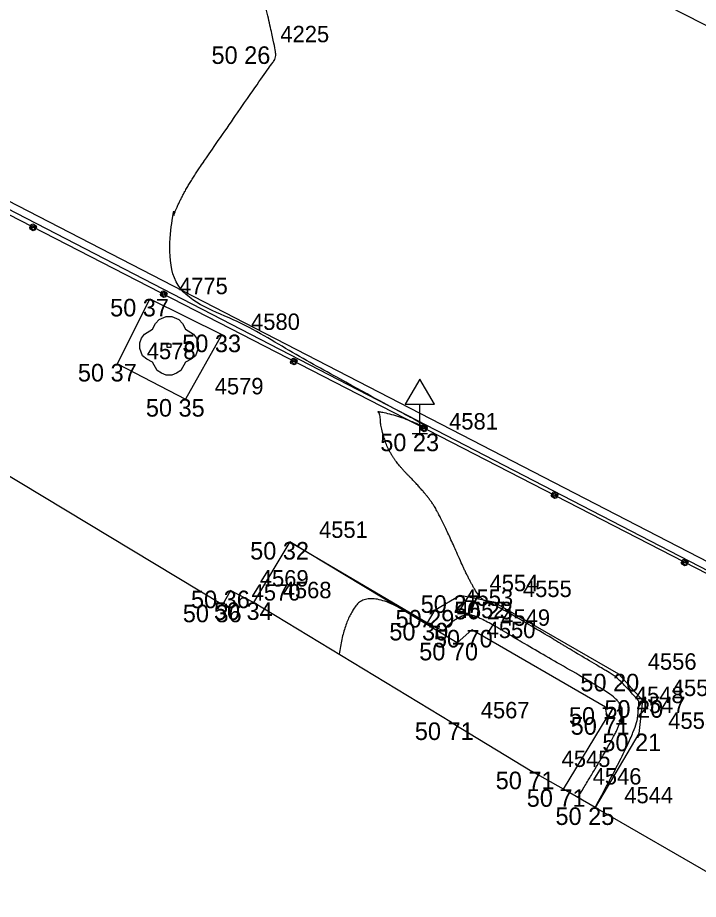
# Model space of a CAD drawing. Extents: x -704017 to -701500, y -1008977 to -1008450.
# Drawn here: x -701790.22 to -701778.61, y -1008943.87 to -1008928.82 of the extents above; entities that cross this region are included whole.
import ezdxf

# ---------------------------------------------------------------- set-up
doc = ezdxf.new("R2010")
doc.units = 0
for name, color, linetype in [('Z_body', 7, 'Continuous'), ('Z_body_cisla', 7, 'Continuous'), ('Z_body_vysky', 7, 'Continuous'), ('Z_budovy', 7, 'Continuous'), ('Z_dopravni_znaceni', 7, 'Continuous'), ('Z_komunikace', 7, 'Continuous'), ('Z_obruby', 7, 'Continuous'), ('Z_rozhrani_ploch', 7, 'Continuous'), ('Z_vrstevnice_vedlejsi', 7, 'Continuous'), ('Z_vstupy', 7, 'Continuous'), ('Z_zabradli', 7, 'Continuous'), ('Z_zelen_jednotliva', 7, 'Continuous')]:
    doc.layers.add(name, color=color, linetype=linetype)

# ---------------------------------------------------------------- blocks, each defined once
blk = doc.blocks.new('POINT_DISPLAY')
blk.add_line((0, 0), (0, 0))
blk = doc.blocks.new('Z530')
for p, q in [((-0.05, 0.03), (-0.03, 0.05)), ((-0.05, -0.03), (-0.05, 0.03)), ((-0.03, 0.05), (0.03, 0.05)), ((-0.03, -0.03), (-0.03, 0.03)), ((-0.03, 0.03), (0.03, 0.03)), ((-0.03, -0.03), (0.03, 0.03)), ((0.03, 0.05), (0.05, 0.03)), ((0.03, 0.03), (0.03, -0.03)), ((0.05, 0.03), (0.05, -0.03)), ((-0.03, -0.05), (-0.05, -0.03)), ((0.03, -0.03), (-0.03, -0.03)), ((0.03, -0.05), (-0.03, -0.05)), ((0.05, -0.03), (0.03, -0.05))]:
    blk.add_line(p, q)
blk = doc.blocks.new('Z527')
for p, q in [((0, 0.93), (-0.25, 0.5)), ((0.25, 0.5), (0, 0.93)), ((-0.25, 0.5), (0.25, 0.5)), ((0, 0), (0, 0.5)), ((-0.13, 0), (0.13, 0))]:
    blk.add_line(p, q)
blk = doc.blocks.new('Z24')
for p, q in [((-0.17, 0.45), (-0.05, 0.5)), ((-0.05, 0.5), (0.05, 0.5)), ((0.05, 0.5), (0.17, 0.45)), ((-0.28, 0.28), (-0.23, 0.38)), ((-0.23, 0.38), (-0.17, 0.45)), ((0.17, 0.45), (0.23, 0.38)), ((0.23, 0.38), (0.28, 0.28)), ((-0.47, 0.13), (-0.42, 0.2)), ((-0.42, 0.2), (-0.28, 0.28)), ((0.28, 0.28), (0.42, 0.2)), ((0.42, 0.2), (0.47, 0.13)), ((-0.5, 0.05), (-0.47, 0.13)), ((-0.5, -0.05), (-0.5, 0.05)), ((-0.03, -0.03), (-0.03, 0.03)), ((-0.03, 0.03), (0.03, 0.03)), ((0.03, 0.03), (0.03, -0.03)), ((0.47, 0.13), (0.5, 0.05)), ((0.5, 0.05), (0.5, -0.05)), ((-0.45, -0.17), (-0.5, -0.05)), ((0.03, -0.03), (-0.03, -0.03)), ((0.5, -0.05), (0.45, -0.17)), ((-0.38, -0.23), (-0.45, -0.17)), ((-0.28, -0.28), (-0.38, -0.23)), ((-0.2, -0.42), (-0.28, -0.28)), ((0.28, -0.28), (0.2, -0.42)), ((0.38, -0.23), (0.28, -0.28)), ((0.45, -0.17), (0.38, -0.23)), ((-0.13, -0.47), (-0.2, -0.42)), ((0.2, -0.42), (0.13, -0.47)), ((-0.05, -0.5), (-0.13, -0.47)), ((0.05, -0.5), (-0.05, -0.5)), ((0.13, -0.47), (0.05, -0.5))]:
    blk.add_line(p, q)

msp = doc.modelspace()

# ---------------------------------------------------------------- linework, layer by layer
at = {"layer": 'Z_budovy'}
for p, q in [((-701786.73, -1008938.84), (-701795, -1008933.86)), ((-701786.59, -1008938.6), (-701786.73, -1008938.84)), ((-701786.2, -1008938.8), (-701786.59, -1008938.6)), ((-701782.82, -1008940.85), (-701786.2, -1008938.8)), ((-701780.91, -1008941.99), (-701781.44, -1008941.69)), ((-701780.37, -1008942.3), (-701780.91, -1008941.99)), ((-701777.65, -1008943.87), (-701780.37, -1008942.3))]:
    msp.add_line(p, q, dxfattribs=at)
at = {"layer": 'Z_komunikace'}
for p, q in [((-701786.47, -1008924.83), (-701776.64, -1008929.9)), ((-701792.33, -1008930.94), (-701777.69, -1008938.5))]:
    msp.add_line(p, q, dxfattribs=at)
at = {"layer": 'Z_obruby'}
msp.add_line((-701777.73, -1008938.63), (-701794.29, -1008930.07), dxfattribs=at)
at = {"layer": 'Z_rozhrani_ploch'}
for p, q in [((-701788.52, -1008934.73), (-701787.97, -1008933.62)), ((-701787.97, -1008933.62), (-701786.74, -1008934.23)), ((-701786.74, -1008934.23), (-701787.36, -1008935.33)), ((-701788.52, -1008934.73), (-701787.36, -1008935.33)), ((-701785.58, -1008937.77), (-701786.2, -1008938.8)), ((-701782.72, -1008939.49), (-701785.58, -1008937.77)), ((-701785.58, -1008937.77), (-701783.23, -1008939.15)), ((-701783.1, -1008938.93), (-701782.67, -1008938.68)), ((-701782.67, -1008938.68), (-701782.1, -1008938.79)), ((-701782.1, -1008938.79), (-701779.97, -1008940.02)), ((-701783.23, -1008939.15), (-701783.1, -1008938.93)), ((-701782.47, -1008939.27), (-701782.72, -1008939.49)), ((-701780.19, -1008940.59), (-701782.47, -1008939.27)), ((-701779.97, -1008940.02), (-701779.56, -1008940.47)), ((-701779.56, -1008940.47), (-701779.62, -1008941.04)), ((-701780.16, -1008940.76), (-701780.19, -1008940.59)), ((-701780.91, -1008941.99), (-701780.16, -1008940.76)), ((-701779.62, -1008941.04), (-701780.37, -1008942.3))]:
    msp.add_line(p, q, dxfattribs=at)
at = {"layer": 'Z_vrstevnice_vedlejsi'}
for points in [[(-701780.37, -1008942.3), (-701779.663, -1008941.018), (-701779.619, -1008940.498), (-701779.622, -1008940.482), (-701779.992, -1008940.076), (-701780.22, -1008939.945), (-701782.116, -1008938.81), (-701782.385, -1008938.735), (-701783.015, -1008937.3), (-701783.273, -1008936.923), (-701783.853, -1008936.331), (-701784.027, -1008935.822), (-701784.036, -1008935.582), (-701784.106, -1008935.525), (-701783.661, -1008935.639), (-701783.182, -1008935.849), (-701783.401, -1008935.701), (-701784.062, -1008935.357), (-701785.982, -1008934.283), (-701788.263, -1008933.04), (-701785.923, -1008929.65), (-701785.816, -1008929.525), (-701785.823, -1008929.336), (-701786.355, -1008927.07), (-701787.003, -1008925.385), (-701787.033, -1008925.191), (-701786.912, -1008924.761), (-701786.955, -1008924.578), (-701786.813, -1008924.647), (-701786.464, -1008924.816), (-701781.758, -1008927.096), (-701779.49, -1008926.403), (-701778.887, -1008926.304), (-701778.837, -1008926.233)], [(-701780.663, -1008942.132), (-701780.256, -1008941.463), (-701779.933, -1008940.878), (-701779.913, -1008940.641), (-701779.931, -1008940.541), (-701780.099, -1008940.355), (-701781.47, -1008939.57), (-701782.313, -1008939.066), (-701782.563, -1008938.996), (-701782.777, -1008939.104), (-701782.905, -1008939.217), (-701782.975, -1008939.32), (-701784.225, -1008938.585), (-701784.653, -1008939.107), (-701784.738, -1008939.686)]]:
    msp.add_open_spline(points, degree=2, dxfattribs=at)
at = {"layer": 'Z_vstupy'}
msp.add_line((-701782.82, -1008940.85), (-701781.44, -1008941.69), dxfattribs=at)
at = {"layer": 'Z_zabradli'}
msp.add_line((-701777.73, -1008938.69), (-701791.57, -1008931.57), dxfattribs=at)

# ---------------------------------------------------------------- block references
at = {"layer": 'Z_body'}
for p in [(-701786.24, -1008929.31), (-701787.97, -1008933.62), (-701786.74, -1008934.23), (-701788.52, -1008934.73), (-701787.36, -1008935.33), (-701783.36, -1008935.92), (-701785.58, -1008937.77), (-701786.59, -1008938.6), (-701782.67, -1008938.68), (-701786.73, -1008938.84), (-701786.2, -1008938.8), (-701782.1, -1008938.79), (-701783.1, -1008938.93), (-701783.23, -1008939.15), (-701782.47, -1008939.27), (-701782.72, -1008939.49), (-701779.97, -1008940.02), (-701779.56, -1008940.47), (-701780.19, -1008940.59), (-701780.16, -1008940.76), (-701782.82, -1008940.85), (-701779.62, -1008941.04), (-701781.44, -1008941.69), (-701780.91, -1008941.99), (-701780.37, -1008942.3)]:
    msp.add_blockref('POINT_DISPLAY', p, dxfattribs=at)
at = {"layer": 'Z_dopravni_znaceni'}
msp.add_blockref('Z527', (-701783.36, -1008935.92), dxfattribs=at)
at = {"layer": 'Z_zabradli', "rotation": 152.8}
for p in [(-701789.96, -1008932.4), (-701787.73, -1008933.54), (-701785.51, -1008934.69), (-701783.29, -1008935.83), (-701781.06, -1008936.97), (-701778.84, -1008938.12)]:
    msp.add_blockref('Z530', p, dxfattribs=at)
at = {"layer": 'Z_zelen_jednotliva'}
msp.add_blockref('Z24', (-701787.64, -1008934.42), dxfattribs=at)

# ---------------------------------------------------------------- texts
at = {"layer": 'Z_body_cisla'}
for s, p in [('4225', (-701785.74, -1008929.24)), ('4775', (-701787.47, -1008933.54)), ('4580', (-701786.24, -1008934.15)), ('4578', (-701788.02, -1008934.65)), ('4579', (-701786.86, -1008935.25)), ('4581', (-701782.86, -1008935.85)), ('4551', (-701785.08, -1008937.7)), ('4569', (-701786.09, -1008938.53)), ('4554', (-701782.17, -1008938.61)), ('4570', (-701786.23, -1008938.77)), ('4568', (-701785.7, -1008938.73)), ('4555', (-701781.6, -1008938.71)), ('4553', (-701782.6, -1008938.86)), ('4552', (-701782.73, -1008939.07)), ('4549', (-701781.97, -1008939.2)), ('4550', (-701782.22, -1008939.41)), ('4556', (-701779.47, -1008939.95)), ('4557', (-701779.06, -1008940.4)), ('4548', (-701779.69, -1008940.52)), ('4567', (-701782.32, -1008940.78)), ('4547', (-701779.66, -1008940.69)), ('4558', (-701779.12, -1008940.96)), ('4545', (-701780.94, -1008941.61)), ('4546', (-701780.41, -1008941.91)), ('4544', (-701779.87, -1008942.23))]:
    msp.add_text(s, height=0.28, dxfattribs=at).set_placement(p)
at = {"layer": 'Z_body_vysky'}
for s, p in [('50 26', (-701786.915, -1008929.61)), ('50 37', (-701788.645, -1008933.92)), ('50 33', (-701787.415, -1008934.53)), ('50 37', (-701789.195, -1008935.03)), ('50 35', (-701788.035, -1008935.63)), ('50 23', (-701784.035, -1008936.22)), ('50 32', (-701786.255, -1008938.07)), ('50 36', (-701787.265, -1008938.9)), ('50 27', (-701783.345, -1008938.98)), ('50 36', (-701787.405, -1008939.14)), ('50 34', (-701786.875, -1008939.1)), ('50 23', (-701782.775, -1008939.09)), ('50 29', (-701783.775, -1008939.23)), ('50 30', (-701783.88, -1008939.45)), ('50 70', (-701783.12, -1008939.57)), ('50 70', (-701783.37, -1008939.79)), ('50 20', (-701780.62, -1008940.32)), ('50 20', (-701780.21, -1008940.77)), ('50 71', (-701780.815, -1008940.89)), ('50 71', (-701780.785, -1008941.06)), ('50 71', (-701783.445, -1008941.15)), ('50 21', (-701780.245, -1008941.34)), ('50 71', (-701782.065, -1008941.99)), ('50 71', (-701781.535, -1008942.29)), ('50 25', (-701781.045, -1008942.6))]:
    msp.add_text(s, height=0.3, dxfattribs=at).set_placement(p)

doc.saveas('drawing.dxf')
